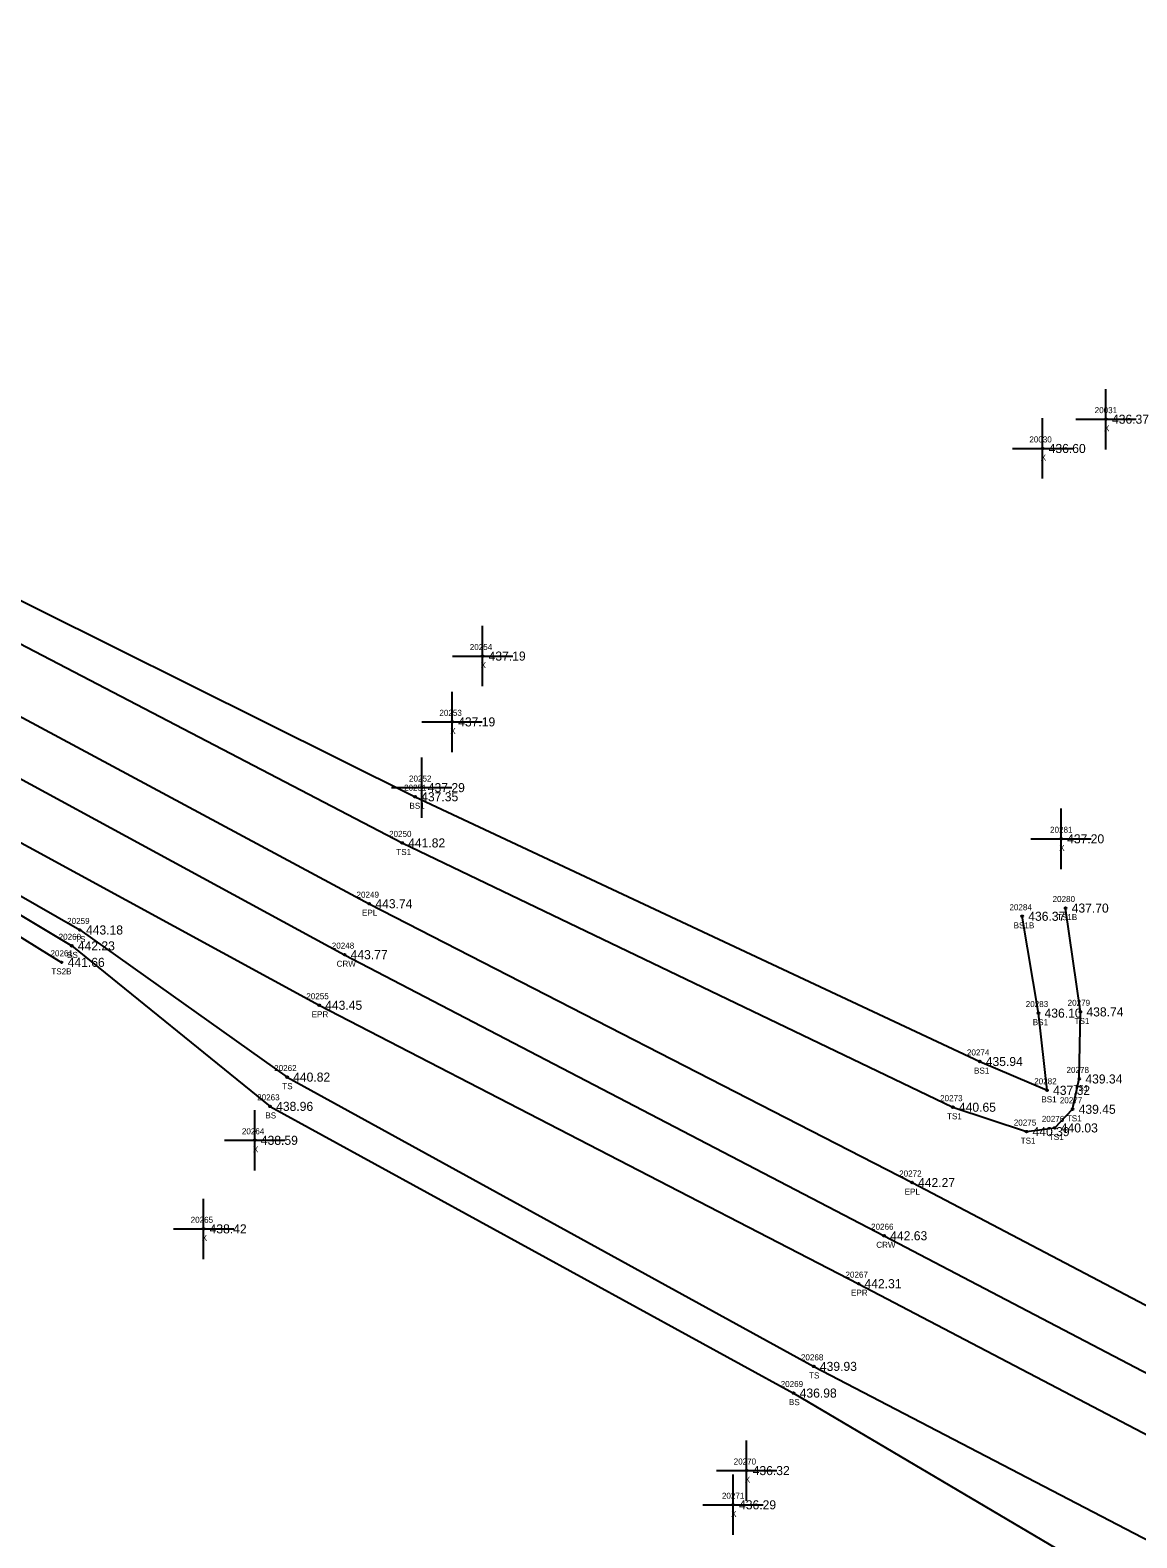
# Model space of a CAD drawing. Extents: x 1810114 to 1811498, y 790790 to 791824.
# Drawn here: x 1810533 to 1810716.3, y 791292.3 to 791542.1 of the extents above; entities that cross this region are included whole.
import ezdxf

# ---------------------------------------------------------------- set-up
doc = ezdxf.new("R2010")
doc.units = 0
for name, color, linetype in [('RD_DTM_BkLn1', 7, 'Continuous'), ('RD_DTM_BkLn2', 7, 'Continuous'), ('RD_DTM_BkLn_txCode', 7, 'Continuous'), ('RD_EX_Misc', 7, 'Continuous'), ('RD_EX_Misc_txCode', 7, 'Continuous'), ('RD_EX_Road', 7, 'Continuous'), ('RD_EX_Road_txCode', 7, 'Continuous'), ('RD_EX_TX_Misc_ELEV', 7, 'Continuous'), ('RD_EX_TX_Road_ELEV', 7, 'Continuous'), ('RD_HC_Survey_ELEV', 7, 'Continuous'), ('RD_HC_Survey_txCode', 7, 'Continuous'), ('RD_SMD_Locator', 7, 'Continuous')]:
    doc.layers.add(name, color=color, linetype=linetype)

msp = doc.modelspace()

# ---------------------------------------------------------------- linework, layer by layer
at = {"layer": 'RD_DTM_BkLn1'}
msp.add_lwpolyline([(1810142.92, 791624.85), (1810231.36, 791577.96), (1810319.85, 791530.5), (1810408.61, 791483.38), (1810496.8, 791436.85), (1810585.08, 791388.93), (1810674.47, 791342.37), (1810763.64, 791295.68)], dxfattribs=at)
at = {"layer": 'RD_DTM_BkLn2'}
for points in [[(1810136.46, 791613.23), (1810225.09, 791566.55), (1810313.34, 791519.56), (1810402.58, 791471.61), (1810490.03, 791423.34), (1810516.06, 791407.46), (1810541.24, 791393.02), (1810575.56, 791368.65), (1810662.82, 791320.73), (1810730.85, 791285.33), (1810742.82, 791282.19), (1810752.34, 791280.87), (1810757.12, 791283.77)], [(1810135.37, 791610.75), (1810224.14, 791564.21), (1810311.68, 791516.56), (1810401.2, 791468.88), (1810488.81, 791421.27), (1810514.98, 791405.31), (1810539.89, 791390.39), (1810572.74, 791363.8), (1810659.47, 791316.31), (1810726.51, 791276.73), (1810738.6, 791270.6), (1810748.52, 791266.73), (1810763.99, 791268.4)], [(1810133.65, 791608.34), (1810222.15, 791560.96), (1810310.01, 791513.91), (1810399.26, 791465.14), (1810487.96, 791419.17), (1810513.17, 791403.16), (1810538.21, 791387.66)], [(1810347.12, 791535.19), (1810346.5, 791532.88), (1810348.47, 791530.85), (1810415.15, 791494.68), (1810464.05, 791470.23), (1810489.27, 791459.14), (1810498.62, 791458.76), (1810506.57, 791453.35), (1810594.61, 791407.44), (1810685.85, 791363.66), (1810698.05, 791359.62), (1810702.73, 791360.23), (1810705.69, 791363.32), (1810706.8, 791368.34), (1810706.98, 791379.45), (1810704.53, 791396.65)], [(1810349.32, 791533.52), (1810415.98, 791496.98), (1810465.1, 791472.47), (1810490.26, 791461.71), (1810499.93, 791461), (1810509.5, 791458.46), (1810596.77, 791415.09), (1810690.3, 791371.23), (1810701.45, 791366.46), (1810700.04, 791379.25), (1810697.34, 791395.29)]]:
    msp.add_lwpolyline(points, dxfattribs=at)
at = {"layer": 'RD_EX_Misc'}
for p, q in [((1810711.21, 791472.63), (1810711.21, 791482.63)), ((1810700.72, 791467.78), (1810700.72, 791477.78)), ((1810706.21, 791477.63), (1810716.21, 791477.63)), ((1810695.72, 791472.78), (1810705.72, 791472.78)), ((1810607.94, 791433.39), (1810607.94, 791443.39)), ((1810602.94, 791438.39), (1810612.94, 791438.39)), ((1810602.9, 791422.49), (1810602.9, 791432.49)), ((1810597.9, 791427.49), (1810607.9, 791427.49)), ((1810597.87, 791411.6), (1810597.87, 791421.6)), ((1810592.87, 791416.6), (1810602.87, 791416.6)), ((1810703.78, 791403.12), (1810703.78, 791413.12)), ((1810698.78, 791408.12), (1810708.78, 791408.12)), ((1810570.21, 791353.18), (1810570.21, 791363.18)), ((1810565.21, 791358.18), (1810575.21, 791358.18)), ((1810561.72, 791338.51), (1810561.72, 791348.51)), ((1810556.72, 791343.51), (1810566.72, 791343.51)), ((1810651.69, 791298.47), (1810651.69, 791308.47)), ((1810646.69, 791303.47), (1810656.69, 791303.47)), ((1810649.43, 791292.8), (1810649.43, 791302.8)), ((1810644.43, 791297.8), (1810654.43, 791297.8))]:
    msp.add_line(p, q, dxfattribs=at)
at = {"layer": 'RD_EX_Road'}
for points in [[(1810147.3, 791633.32), (1810235.73, 791586.37), (1810316.89, 791542.45), (1810324.32, 791538.42), (1810350.04, 791524.6), (1810412.94, 791490.75), (1810461.45, 791466.07), (1810501.18, 791444.55), (1810589.18, 791397.37), (1810679.08, 791351.18), (1810768.4, 791304.34)], [(1810138.18, 791616.8), (1810226.92, 791569.59), (1810315.11, 791521.87), (1810404.37, 791475.11), (1810492.73, 791428.56), (1810580.86, 791380.55), (1810670.21, 791334.43), (1810759.54, 791287.61)]]:
    msp.add_lwpolyline(points, dxfattribs=at)
at = {"layer": 'RD_SMD_Locator'}
for centre in [(1810711.21, 791477.63), (1810700.72, 791472.78), (1810607.94, 791438.39), (1810602.9, 791427.49), (1810596.77, 791415.09), (1810597.87, 791416.6), (1810594.61, 791407.44), (1810703.78, 791408.12), (1810589.18, 791397.37), (1810697.34, 791395.29), (1810704.53, 791396.65), (1810541.24, 791393.02), (1810539.89, 791390.39), (1810538.21, 791387.66), (1810585.08, 791388.93), (1810580.86, 791380.55), (1810700.04, 791379.25), (1810706.98, 791379.45), (1810690.3, 791371.23), (1810575.56, 791368.65), (1810706.8, 791368.34), (1810701.45, 791366.46), (1810572.74, 791363.8), (1810685.85, 791363.66), (1810705.69, 791363.32), (1810702.73, 791360.23), (1810570.21, 791358.18), (1810698.05, 791359.62), (1810679.08, 791351.18), (1810561.72, 791343.51), (1810674.47, 791342.37), (1810670.21, 791334.43), (1810662.82, 791320.73), (1810659.47, 791316.31), (1810651.69, 791303.47), (1810649.43, 791297.8)]:
    msp.add_circle(centre, 0.15, dxfattribs=at)

# ---------------------------------------------------------------- texts
at = {"layer": 'RD_DTM_BkLn_txCode'}
for s, p in [('20251', (1810594.94, 791416.09)), ('BS1', (1810595.83, 791413.09)), ('20250', (1810592.45, 791408.44)), ('TS1', (1810593.65, 791405.44)), ('20280', (1810702.37, 791397.65)), ('20259', (1810539.12, 791394.02)), ('20284', (1810695.22, 791396.29)), ('TS1B', (1810703.1, 791394.65)), ('BS1B', (1810695.92, 791393.29)), ('20260', (1810537.71, 791391.39)), ('TS', (1810540.45, 791391.02)), ('20261', (1810536.36, 791388.66)), ('BS', (1810539.11, 791388.39)), ('TS2B', (1810536.5, 791385.66)), ('20283', (1810697.92, 791380.25)), ('20279', (1810704.86, 791380.45)), ('BS1', (1810699.09, 791377.25)), ('TS1', (1810706.02, 791377.45)), ('20274', (1810688.18, 791372.23)), ('20262', (1810573.42, 791369.65)), ('BS1', (1810689.36, 791369.23)), ('20278', (1810704.68, 791369.34)), ('TS', (1810574.76, 791366.65)), ('20282', (1810699.33, 791367.46)), ('20263', (1810570.6, 791364.8)), ('20273', (1810683.74, 791364.66)), ('BS1', (1810700.51, 791364.46)), ('20277', (1810703.57, 791364.32)), ('TS1', (1810705.84, 791366.34)), ('BS', (1810571.96, 791361.8)), ('TS1', (1810684.89, 791361.66)), ('20275', (1810695.94, 791360.62)), ('20276', (1810700.58, 791361.23)), ('TS1', (1810704.73, 791361.32)), ('TS1', (1810697.09, 791357.62)), ('TS1', (1810701.76, 791358.23)), ('20268', (1810660.68, 791321.73)), ('20269', (1810657.32, 791317.31)), ('TS', (1810662.03, 791318.73)), ('BS', (1810658.69, 791314.31))]:
    msp.add_text(s, height=1, dxfattribs=at).set_placement(p)
at = {"layer": 'RD_EX_Misc_txCode'}
for s, p in [('20031', (1810709.34, 791478.63)), ('X', (1810710.89, 791475.63)), ('20030', (1810698.52, 791473.78)), ('X', (1810700.4, 791470.78)), ('20254', (1810605.82, 791439.39)), ('X', (1810607.62, 791436.39)), ('20253', (1810600.79, 791428.49)), ('X', (1810602.59, 791425.49)), ('20252', (1810595.75, 791417.6)), ('X', (1810597.56, 791414.6)), ('20281', (1810701.95, 791409.12)), ('X', (1810703.47, 791406.12)), ('20264', (1810568.07, 791359.18)), ('X', (1810569.9, 791356.18)), ('20265', (1810559.58, 791344.51)), ('X', (1810561.41, 791341.51)), ('20270', (1810649.54, 791304.47)), ('X', (1810651.38, 791301.47)), ('20271', (1810647.59, 791298.8)), ('X', (1810649.11, 791295.8))]:
    msp.add_text(s, height=1, dxfattribs=at).set_placement(p)
at = {"layer": 'RD_EX_Road_txCode'}
for s, p in [('20249', (1810587.06, 791398.37)), ('EPL', (1810587.97, 791395.37)), ('20255', (1810578.74, 791381.55)), ('EPR', (1810579.63, 791378.55)), ('20272', (1810676.96, 791352.18)), ('EPL', (1810677.87, 791349.18)), ('20267', (1810668.06, 791335.43)), ('EPR', (1810668.98, 791332.43))]:
    msp.add_text(s, height=1, dxfattribs=at).set_placement(p)
at = {"layer": 'RD_EX_TX_Misc_ELEV'}
for s, p in [('436.37', (1810712.21, 791476.88)), ('436.60', (1810701.72, 791472.03)), ('437.19', (1810608.94, 791437.64)), ('437.19', (1810603.9, 791426.74)), ('437.35', (1810597.77, 791414.34)), ('437.29', (1810598.87, 791415.85)), ('441.82', (1810595.61, 791406.69)), ('437.20', (1810704.78, 791407.37)), ('437.70', (1810705.53, 791395.9)), ('436.37', (1810698.34, 791394.54)), ('443.18', (1810542.24, 791392.27)), ('442.23', (1810540.89, 791389.64)), ('441.66', (1810539.21, 791386.91)), ('436.10', (1810701.04, 791378.5)), ('438.74', (1810707.98, 791378.7)), ('435.94', (1810691.3, 791370.48)), ('440.82', (1810576.56, 791367.9)), ('439.34', (1810707.8, 791367.59)), ('437.32', (1810702.45, 791365.71)), ('438.96', (1810573.74, 791363.05)), ('440.65', (1810686.85, 791362.91)), ('439.45', (1810706.69, 791362.57)), ('440.39', (1810699.05, 791358.87)), ('440.03', (1810703.73, 791359.48)), ('438.59', (1810571.21, 791357.43)), ('438.42', (1810562.72, 791342.76)), ('439.93', (1810663.82, 791319.98)), ('436.98', (1810660.47, 791315.56)), ('436.32', (1810652.69, 791302.72)), ('436.29', (1810650.43, 791297.05))]:
    msp.add_text(s, height=1.5, dxfattribs=at).set_placement(p)
at = {"layer": 'RD_EX_TX_Road_ELEV'}
for s, p in [('443.74', (1810590.18, 791396.62)), ('443.45', (1810581.86, 791379.8)), ('442.27', (1810680.08, 791350.43)), ('442.31', (1810671.21, 791333.68))]:
    msp.add_text(s, height=1.5, dxfattribs=at).set_placement(p)
at = {"layer": 'RD_HC_Survey_ELEV'}
for s, p in [('443.77', (1810586.08, 791388.18)), ('442.63', (1810675.47, 791341.62))]:
    msp.add_text(s, height=1.5, dxfattribs=at).set_placement(p)
at = {"layer": 'RD_HC_Survey_txCode'}
for s, p in [('20248', (1810582.96, 791389.93)), ('CRW', (1810583.76, 791386.93)), ('20266', (1810672.3, 791343.37)), ('CRW', (1810673.16, 791340.37))]:
    msp.add_text(s, height=1, dxfattribs=at).set_placement(p)

doc.saveas('drawing.dxf')
